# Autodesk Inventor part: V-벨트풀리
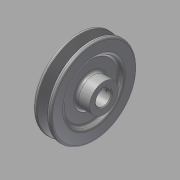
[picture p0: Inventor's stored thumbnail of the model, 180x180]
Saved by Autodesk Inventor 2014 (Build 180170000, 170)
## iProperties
Created: 2015-09
Part Number: V-벨트풀리
Material: 강철, 연강
Document SubType Name: Modeling
Designer: mduedu
Density: 7.86 g/cm^3
Appearance: 강철
Mass: 779.077 g
Surface Area: 277.465 cm^2
Volume: 99.1192 cm^3
Author: mduedu
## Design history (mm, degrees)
sketch "스케치1"
  geometry: L1 (-10, 0)-(10, 0); L2 (-10, 0)-(-10, 48); L3 (-10, 48)-(-5.976, 48); L4 (-5.976, 48)-(-2.154, 35.5); L5 (-2.154, 35.5)-(2.154, 35.5); L6 (2.154, 35.5)-(5.976, 48); L7 (5.976, 48)-(10, 48); L8 (10, 48)-(10, 0); L9 (0, 0)-(0, 35.5); L10 (-10, 43.5)-(10, 43.5); 3 further points
  constraints: 20 end point, 6 point on line, 3 perpendicular, 2 midpoint, 2 parallel, 2 symmetric about line, 1 coincident, 1 collinear, 1 equal length, 1 horizontal, 1 vertical, 1 vertical alignment
  dimensions: "d0" = 20 distance between parallel lines of L8 L2; "d2" = 96 diameter of L3 L1; "d3" = 87 diameter of L10 L1; "d4" = 4.5 distance between parallel lines of L10 L3 (derived); "d5" = 8 distance between parallel lines of L5 L10; "d6" = 9.2 distance of point (4.6, 43.5) point (-4.6, 43.5); "d7" = 34 deg angle of L6 L4
revolve "회전1" sketch "스케치1" stored, may be unused: angle "d8" = 90 deg
sketch "스케치2"
  geometry: C1 r 16 at (0, 0); 1 further point
  constraints: 1 centre point, 1 coincident
  dimensions: "d9" = 32 diameter of C1
extrude "돌출1" join sketch "스케치2" distance "d10" = 11; taper "d11" = 0 deg
fillet "모깎기1" dims "d12" = 1, "d13" = 0.5, "d14" = 2
sketch "스케치3"
  geometry: C1 r 16 at (0, 0) reference; C2 r 32 at (0, 0); 1 further point
  constraints: 1 centre point, 1 coincident
  dimensions: "d15" = 64 diameter of C2
extrude "돌출2" cut sketch "스케치3" distance "d16" = 4; taper "d17" = 0 deg
fillet "모깎기2" dims "d18" = 3
fillet "모깎기3" dims "d19" = 3
fillet "모깎기4" dims "d20" = 3
sketch "스케치4"
  geometry: C1 r 8.5 at (0, 0); 1 further point
  constraints: 1 centre point, 1 coincident
  dimensions: "d21" = 17 diameter of C1
extrude "돌출3" cut sketch "스케치4" stored distance "d22" = 4; taper "d23" = 0 deg
sketch "스케치5"
  geometry: L1 (-2.5, 8.124)-(2.5, 8.124); L2 (2.5, 8.124)-(2.5, 10.8); L3 (2.5, 10.8)-(-2.5, 10.8); L4 (-2.5, 10.8)-(-2.5, 8.124); A1 r 8.5 centre (0, 0) between (-2.5, 8.124) and (2.5, 8.124) reference; 2 further points
  constraints: 8 end point, 3 point on circle, 2 parallel, 1 horizontal, 1 perpendicular, 1 vertical alignment
  dimensions: "d24" = 5 distance of L2.end L3.end; "d26" = 19.3 distance from line of L3 point (0, -8.5)
extrude "돌출4" cut sketch "스케치5" stored distance "d27" = 4; taper "d28" = 0 deg
chamfer "모따기1" distance "d29" = 1; stored, may be unused: second distance "d30" = 2, angle "d31" = 45 deg
node "작업 평면1"
sketch "스케치6"
  geometry: L1 (-11, 16)-(-11, -16) reference; 2 further points
  constraints: 1 horizontal alignment
  dimensions: "d32" = 5 distance from line of point (-6, 0) L1
hole "구멍1" sketch "스케치6" at (-6, 0) diameter "d33" = 3.242; stored, may be unused: countersink angle "d37" = 90 deg, drill point angle "d39" = 118 deg; dims "d34" = 6, "d35" = 4, "d36" = 2, "d38" = 8
node "솔리드1"
mirror "대칭1"
